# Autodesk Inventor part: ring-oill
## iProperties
Created: 2002-08
Part Number: ring-oill
Document SubType Name: Modeling
Designer: t_munrn
Density: 1 g/cm^3
Control State: 0
Master: False
Checked Out: False
Shininess: 64.0
Length Units: 11269
Angle Units: 11279
Time Units: 11290
Mass Units: 11283
Length Display Precision: 3
Angle Display Precision: 2
Compacted: True
Density: 0.0
Volumn: 0.0
Area: 0.0
PropertySet Name: Model Information
Author: t_munrn
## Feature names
1. Revolution1
2. Mirror1
3. Extrusion1
4. Circular Pattern1
